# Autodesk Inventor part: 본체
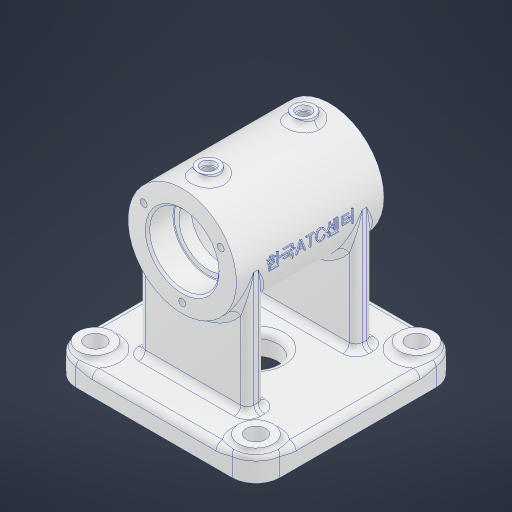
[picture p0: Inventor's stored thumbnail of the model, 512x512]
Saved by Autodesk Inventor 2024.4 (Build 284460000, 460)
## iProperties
Created: 2025-10
Part Number: 본체
Material: 알루미늄 6061
Document SubType Name: Modeling
Designer: user
Density: 2.7 g/cm^3
Appearance: 알루미늄 - 평지
Mass: 504.517 g
Surface Area: 500.128 cm^2
Volume: 186.858 cm^3
Author: user
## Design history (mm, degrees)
sketch "스케치1"
  geometry: C1 r 25 at (0, 0); 1 further point
  constraints: 1 centre point, 1 coincident
  dimensions: "d0" = 50 diameter of C1
extrude "돌출1" new body sketch "스케치1" stored distance "d1" = 68; taper "d2" = 0 deg
sketch "스케치2"
  geometry: L1 (-25, -34)-(25, -34) reference; L2 (25, 34)-(-25, 34) reference; L3 (0, 34)-(0, -34); L4 (16, 34)-(16, 22.3); L5 (15.7, 22)-(13.5, 22); L6 (13.5, 22)-(13.5, 16.258); L7 (13.5, 16.258)-(20, 5); L8 (20, 5)-(20, -5); L9 (20, -5)-(13.5, -16.258); L10 (13.5, -16.258)-(13.5, -22); L11 (13.5, -22)-(15.7, -22); L12 (16, -22.3)-(16, -34); L13 (25, -34)-(25, 34) reference; L14 (16, 34)-(0, 34); L15 (16, -34)-(0, -34); A1 r 0.3 centre (15.7, 22.3) between (15.7, 22) and (16, 22.3); A2 r 0.3 centre (15.7, -22.3) between (16, -22.3) and (15.7, -22); 6 further points
  constraints: 24 end point, 10 point on line, 5 midpoint, 4 perpendicular, 4 point on circle, 4 tangent, 2 centre point, 2 collinear, 1 horizontal alignment, 1 parallel
  dimensions: "d3" = 10 distance of L7.end L8.end; "d4" = 12 distance of L4.start point (16, 22); "d5" = 40 diameter of point (20, 0) point (0, 0); "d6" = 32 diameter of L12 L3; "d7" = 27 diameter of L10 L3; "d8" = 0.3 radius of A1; "d9" = 30 deg angle of L3 L7; "d10" = 0.3 radius of A2
revolve "회전1" sketch "스케치2" stored, may be unused: angle "d11" = 90 deg
chamfer "모따기1" distance "d12" = 1; stored, may be unused: second distance "d13" = 2, angle "d14" = 45 deg
fillet "모깎기1" dims "d15" = 3
sketch "스케치3"
  geometry: L1 (-25, -34)-(25, -34) reference; L2 (25, 34)-(-25, 34) reference; L3 (-17, 34)-(-16, 33) reference; L4 (-16, 33)-(-16, 22.3) reference; L5 (-15.7, 22)-(-13.5, 22) reference; L6 (-13.5, 22)-(-13.5, 16.258) reference; L7 (-13.5, 16.258)-(-19.598, 5.696) reference; L8 (-20, 4.196)-(-20, -4.196) reference; L9 (-19.598, -5.696)-(-13.5, -16.258) reference; L10 (-13.5, -16.258)-(-13.5, -22) reference; L11 (-13.5, -22)-(-15.7, -22) reference; L12 (-16, -22.3)-(-16, -33) reference; L13 (-16, -33)-(-17, -34) reference; L14 (-17, -34)-(-25, -34) reference; L15 (-25, -34)-(-25, 34) reference; L16 (-25, 34)-(-17, 34) reference; L17 (16, 33)-(17, 34) reference; L18 (17, 34)-(25, 34) reference; L19 (25, 34)-(25, -34) reference; L20 (25, -34)-(17, -34) reference; L21 (17, -34)-(16, -33) reference; L22 (16, -33)-(16, -22.3) reference; L23 (15.7, -22)-(13.5, -22) reference; L24 (13.5, -22)-(13.5, -16.258) reference; L25 (13.5, -16.258)-(19.598, -5.696) reference; L26 (20, -4.196)-(20, 4.196) reference; L27 (19.598, 5.696)-(13.5, 16.258) reference; L28 (13.5, 16.258)-(13.5, 22) reference; L29 (13.5, 22)-(15.7, 22) reference; L30 (16, 22.3)-(16, 33) reference; L31 (25, 22)-(28, 22); L32 (28, 22)-(28, 27); L33 (28, 27)-(25, 27); L34 (25, 27)-(23, 27); L35 (23, 27)-(23, 22); L36 (23, 22)-(25, 22); A1 r 0.3 centre (-15.7, 22.3) between (-16, 22.3) and (-15.7, 22) reference; A2 r 3 centre (-17, 4.196) between (-19.598, 5.696) and (-20, 4.196) reference; A3 r 3 centre (-17, -4.196) between (-20, -4.196) and (-19.598, -5.696) reference; A4 r 0.3 centre (-15.7, -22.3) between (-15.7, -22) and (-16, -22.3) reference; A5 r 0.3 centre (15.7, -22.3) between (16, -22.3) and (15.7, -22) reference; A6 r 3 centre (17, -4.196) between (19.598, -5.696) and (20, -4.196) reference; A7 r 3 centre (17, 4.196) between (20, 4.196) and (19.598, 5.696) reference; A8 r 0.3 centre (15.7, 22.3) between (15.7, 22) and (16, 22.3) reference; 1 further point
  constraints: 12 end point, 3 horizontal, 2 perpendicular, 1 parallel, 1 point on line
  dimensions: "d16" = 12 vertical distance of L2.start L31.end; "d17" = 3 distance from line of L19 L32.end; "d18" = 10 diameter of L32.end L31; "d19" = 5 distance between parallel lines of L35 L32
revolve "회전2" sketch "스케치3" stored, may be unused: angle "d20" = 90 deg
fillet "모깎기2" dims "d21" = 3
sketch "스케치4"
  geometry: A1 r 5 centre (0, 0) between (0, -5) and (0, 5) reference; A2 r 5 centre (0, 0) between (0, 5) and (0, -5) reference; A3 r 5 centre (0, 44) between (0, 49) and (0, 39) reference; A4 r 5 centre (0, 44) between (0, 39) and (0, 49) reference; 3 further points
  constraints: 2 coincident
hole "구멍1" sketch "스케치4" at (0, 44), (0, 0) diameter "d22" = 5.1881; stored, may be unused: countersink angle "d26" = 90 deg, drill point angle "d28" = 0 deg; dims "d23" = 12, "d24" = 6.6, "d25" = 2, "d27" = 11.8
node "작업 평면1"
sketch "스케치5"
  geometry: L1 (47, -25)-(-47, -25); L2 (-47, -25)-(-47, 69); L3 (-47, 69)-(47, 69); L4 (47, 69)-(47, -25); L5 (47, -25)-(-47, 69); L6 (-47, -25)-(47, 69); L7 (37, -15)-(-37, -15); L8 (-37, -15)-(-37, 59); L9 (-37, 59)-(37, 59); L10 (37, 59)-(37, -15); L11 (37, -15)-(-37, 59); L12 (-37, -15)-(37, 59); C1 r 8 at (-37, -15); C2 r 4.5 at (-37, -15); C3 r 4.5 at (37, -15); C4 r 4.472 at (37, -15); C5 r 4.5 at (37, 59); C6 r 8 at (37, 59); C7 r 8 at (-37, 59); C8 r 4.5 at (-37, 59); C9 r 8 at (37, -15); 1 further point
  constraints: 24 end point, 9 centre point, 9 coincident, 6 equal radius, 4 midpoint, 4 parallel, 4 perpendicular, 2 horizontal
  dimensions: "d30" = 94 distance of L1.end L2.end; "d31" = 16 diameter of C1; "d32" = 9 diameter of C2; "d33" = 74 distance of L7.start L7.end
extrude "돌출2" join sketch "스케치5" distance "d34" = 13; taper "d35" = 0 deg
extrude "돌출3" join sketch "스케치5" distance "d36" = 10; taper "d37" = 0 deg
fillet "모깎기3" dims "d38" = 11
fillet "모깎기4" dims "d39" = 3
fillet "모깎기5" dims "d40" = 3
sketch "스케치6"
  geometry: L1 (-19.389, 25)-(-56, 25); L2 (-0.488, 21)-(-56, 21); L3 (-0.488, 29)-(-56, 29); L4 (-56, 29)-(-56, 21); L5 (28, 27)-(28, 25.3) reference; L6 (28, 25.3)-(26, 25.3) reference; L7 (26, 25.3)-(26, 24.594) reference; L8 (26, 24.594)-(16, 24.594) reference; L9 (16, 24.594)-(16, 33) reference; L10 (16, 33)-(17, 34) reference; L11 (17, 34)-(25, 34) reference; L12 (25, 34)-(25, 30) reference; L13 (19.598, 5.696)-(13.5, 16.258) reference; L14 (13.5, 16.258)-(13.5, 19.406) reference; L15 (13.5, 19.406)-(26, 19.406) reference; L16 (26, 19.406)-(26, 18.7) reference; L17 (26, 18.7)-(28, 18.7) reference; L18 (28, 18.7)-(28, 17) reference; L19 (25, 14)-(25, -14) reference; L20 (28, -17)-(28, -18.7) reference; L21 (28, -18.7)-(26, -18.7) reference; L22 (26, -18.7)-(26, -19.406) reference; L23 (26, -19.406)-(13.5, -19.406) reference; L24 (13.5, -19.406)-(13.5, -16.258) reference; L25 (13.5, -16.258)-(19.598, -5.696) reference; L26 (20, -4.196)-(20, 4.196) reference; L27 (-16, -33)-(-17, -34) reference; L28 (-17, -34)-(-25, -34) reference; L29 (-25, -34)-(-25, 34) reference; L30 (-25, 34)-(-17, 34) reference; L31 (-17, 34)-(-16, 33) reference; L32 (-16, 33)-(-16, 22.3) reference; L33 (-15.7, 22)-(-13.5, 22) reference; L34 (-13.5, 22)-(-13.5, 16.258) reference; L35 (-13.5, 16.258)-(-19.598, 5.696) reference; L36 (-20, 4.196)-(-20, -4.196) reference; L37 (-19.598, -5.696)-(-13.5, -16.258) reference; L38 (-13.5, -16.258)-(-13.5, -22) reference; L39 (-13.5, -22)-(-15.7, -22) reference; L40 (-16, -22.3)-(-16, -33) reference; L41 (17, -34)-(16, -33) reference; L42 (16, -33)-(16, -24.594) reference; L43 (16, -24.594)-(26, -24.594) reference; L44 (26, -24.594)-(26, -25.3) reference; L45 (26, -25.3)-(28, -25.3) reference; L46 (28, -25.3)-(28, -27) reference; L47 (25, -30)-(25, -34) reference; L48 (25, -34)-(17, -34) reference; L49 (-56, 44)-(-56, -44) reference; L50 (-59, -47)-(-66, -47) reference; L51 (-66, -47)-(-66, 47) reference; L52 (-66, 47)-(-59, 47) reference; A1 r 3 centre (17, 4.196) between (20, 4.196) and (19.598, 5.696) reference; A2 r 3 centre (17, -4.196) between (19.598, -5.696) and (20, -4.196) reference; A3 r 0.3 centre (-15.7, 22.3) between (-16, 22.3) and (-15.7, 22) reference; A4 r 3 centre (-17, 4.196) between (-19.598, 5.696) and (-20, 4.196) reference; A5 r 3 centre (-17, -4.196) between (-20, -4.196) and (-19.598, -5.696) reference; A6 r 0.3 centre (-15.7, -22.3) between (-15.7, -22) and (-16, -22.3) reference; A7 r 3 centre (-59, 44) between (-56, 44) and (-59, 47) reference; A8 r 3 centre (-59, -44) between (-59, -47) and (-56, -44) reference; 3 further points; 1 other entity
  constraints: 8 end point, 2 parallel, 2 point on line, 1 horizontal, 1 vertical, 7 other
  dimensions: "d42" = 4 distance between parallel lines of L1 L2; "d43" = 4 distance between parallel lines of L1 L3; "d44" = 21 distance from line of L2 point (0, 0)
  node "절단 모서리 투영3"
node "작업 평면2"
sketch "스케치8"
  geometry: 2 further points
  constraints: 1 coincident
hole "구멍2" sketch "스케치8" at (0, 22) diameter "d52" = 20; stored, may be unused: countersink angle "d56" = 90 deg, drill point angle "d58" = 0 deg; dims "d53" = 12, "d54" = 6.6, "d55" = 2, "d57" = 8
fillet "모깎기6" dims "d59" = 3
node "작업 평면3"
sketch "스케치9"
  geometry: C1 r 13 at (0, -22) reference; C2 r 6 at (0, -22); 1 further point
  constraints: 1 centre point, 1 coincident
  dimensions: "d61" = 12 diameter of C2
extrude "돌출5" join sketch "스케치9" stored distance "d62" = 13; taper "d63" = 0 deg
fillet "모깎기7" dims "d64" = 3
sketch "스케치10"
  geometry: A1 r 6 centre (0, 22) between (0, 28) and (0, 16) reference; 1 further point
  constraints: 1 coincident
hole "구멍3" sketch "스케치10" at (0, 22) diameter "d65" = 5.1881; stored, may be unused: countersink angle "d69" = 90 deg, drill point angle "d71" = 0 deg; dims "d66" = 12, "d67" = 4, "d68" = 2, "d70" = 28.5
sketch "스케치11"
  geometry: L1 (-63.097, 29)-(6.356, 29); 1 further point
  constraints: 2 end point, 1 horizontal
  dimensions: "d72" = 29 distance from line of L1 point (0, 0)
feature "리브1" sketch "스케치11" dims "d73" = 8, "d74" = 25, "d75" = 0, "d76" = 0, "d77" = 1, "d78" = 1
fillet "모깎기8" dims "d79" = 3
fillet "모깎기14" dims "d85" = 3
fillet "모깎기15" dims "d86" = 3
sketch "스케치7" dims "d0" = 50
  geometry: L1 (-66, 36)-(-66, -36) reference; 3 further points
  constraints: 1 coincident, 1 horizontal alignment, 1 midpoint, 1 other
  dimensions: "d87" = 66 distance from line of L1 point (0, 0)
feature "엠보싱1" sketch "스케치7" dims "d0" = 50, "d3" = 10, "d4" = 12, "d5" = 40, "d6" = 32, "d7" = 27, "d8" = 0.3, "d9" = 30 deg, "d10" = 0.3, "d50" = 0.5, "d51" = 0
sketch "스케치12" dims "d88" = 41
  geometry: C1 r 25 at (0, 0) reference; C2 r 17 at (0, 0) reference; 4 further points
  constraints: 2 vertical alignment, 1 coincident, 6 other
  dimensions: "d91" = 360 deg dimension on point (0, 0) point (0, -20.5) (derived)
hole "구멍4" sketch "스케치12" at (0, -20.5), (17.754, 10.25), (-17.754, 10.25) diameter "d93" = 3.242; stored, may be unused: countersink angle "d97" = 82 deg, drill point angle "d99" = 118 deg; dims "d94" = 8, "d95" = 3.023, "d96" = 2, "d98" = 10
node "솔리드1"
mirror "미러1"
mirror "미러2"
mirror "미러3"
mirror "미러4"
node "투영된 루프1"
node "투영된 루프2"
node "절단 모서리 투영1"
node "절단 모서리 투영2"
feature "A9D066F2-1C7D-4E18-AEED-F7BC21143FA4" dims "d52" = 20, "d53" = 12, "d54" = 6.6, "d55" = 2, "d56" = 90 deg, "d57" = 8, "d58" = 0
other parameters: "d29" = -94, "d60" = -56
